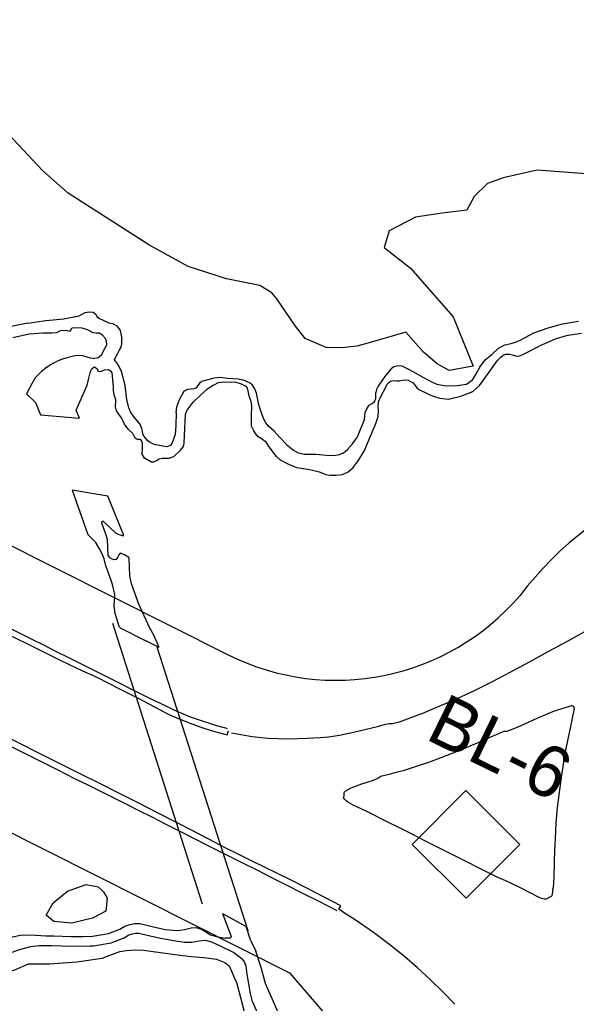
# Model space of a CAD drawing. Extents: x 1517485 to 1521905, y 636528 to 640355.
# Drawn here: x 1519895.6 to 1520112.8, y 638285.4 to 638668.8 of the extents above; entities that cross this region are included whole.
import ezdxf

# ---------------------------------------------------------------- set-up
doc = ezdxf.new("R2010")
doc.units = 0
for name, color, linetype in [('CTL Secondary Horizontal and Vertical CELL', 7, 'Continuous'), ('CTL Secondary Horizontal and Vertical Text', 7, 'Continuous'), ('Exist Hydro Stream or Body of Water', 7, 'Continuous'), ('Exist Right of Way Line', 7, 'Continuous'), ('Exist Roads Curbs', 7, 'Continuous'), ('Exist Roads EOP', 7, 'Continuous'), ('Exist Structure Major Deck Tunnel Box Culvert', 7, 'Continuous'), ('Exist Vegetation Woods Line', 7, 'Continuous')]:
    doc.layers.add(name, color=color, linetype=linetype)

msp = doc.modelspace()

# ---------------------------------------------------------------- linework, layer by layer
at = {"layer": 'CTL Secondary Horizontal and Vertical CELL'}
msp.add_line((1520069.61, 638347.3), (1520069.61, 638347.3), dxfattribs=at)
msp.add_lwpolyline([(1520048.75, 638347.37), (1520069.72, 638368.34), (1520090.72, 638347.34), (1520069.75, 638326.37)], close=True, dxfattribs=at)
at = {"layer": 'Exist Hydro Stream or Body of Water'}
for p, q in [((1519898.81, 638550.48), (1519891.63, 638549.08)), ((1519899.36, 638546.22), (1519893.03, 638544.8)), ((1519959.93, 638506.77), (1519960.29, 638515.04)), ((1520030.18, 638513.06), (1520027.09, 638505.85)), ((1520031.47, 638504.02), (1520034.55, 638511.39)), ((1519934.58, 638431.95), (1519945.16, 638426.56)), ((1519950.02, 638424.07), (1519945.16, 638426.56)), ((1519974.77, 638320.41), (1519983.95, 638315.43)), ((1519985.8, 638309.77), (1519983.95, 638315.43)), ((1519909.03, 638311.73), (1519915.59, 638311.43)), ((1519908.36, 638307.93), (1519915.57, 638307.66)), ((1519915.57, 638307.66), (1519923.09, 638307.77)), ((1519985.8, 638309.77), (1519987.7, 638305.7))]:
    msp.add_line(p, q, dxfattribs=at)
for points in [[(1519898.81, 638550.48), (1519905.84, 638551.5), (1519912.91, 638552.26), (1519918.81, 638553.38), (1519921.21, 638554.69), (1519922.8, 638554.89), (1519924.25, 638554.77), (1519925.4, 638554.06), (1519925.8, 638553.07), (1519926.53, 638552.41), (1519930.37, 638550.68), (1519931.86, 638550.36), (1519933.54, 638549.42), (1519934.83, 638547.6), (1519935.45, 638544.42)], [(1520096.22, 638546.71), (1520101.74, 638548.73), (1520107.41, 638550.25), (1520113.66, 638551.31)], [(1519929.15, 638544.59), (1519927.97, 638545.88), (1519926.6, 638546.64), (1519925.46, 638546.58), (1519924.37, 638546.71), (1519922.14, 638547.95), (1519920.02, 638548.61), (1519916.46, 638548.63), (1519915.84, 638548.39), (1519915.18, 638547.23), (1519914.19, 638547.53), (1519912.39, 638547.69), (1519911.16, 638547.41), (1519909.96, 638546.71), (1519908.14, 638546.66), (1519904.62, 638546.64), (1519899.36, 638546.22)], [(1520079.79, 638538.28), (1520082.42, 638540.8), (1520084.89, 638542.12), (1520087.4, 638542.63), (1520089.44, 638543.27), (1520091.08, 638544.05), (1520096.22, 638546.71)], [(1520114.82, 638546.45), (1520108.84, 638545.59), (1520104.45, 638544.21), (1520098.32, 638541.51)], [(1519924.3, 638536.79), (1519926.21, 638537.07), (1519927.53, 638538.2), (1519928.89, 638540.62), (1519929.58, 638542.12), (1519929.54, 638543.51), (1519929.15, 638544.59)], [(1519933.11, 638535.39), (1519932.67, 638536.2), (1519933.11, 638537.41), (1519933.76, 638538.56), (1519934.5, 638539.88), (1519935.04, 638540.87), (1519935.45, 638542.36), (1519935.45, 638544.42)], [(1520081.93, 638535.82), (1520083.31, 638537.31), (1520084.19, 638538.1), (1520085.31, 638538.49), (1520086.75, 638538.4), (1520088.28, 638538.05), (1520089.48, 638537.6), (1520090.72, 638537.78), (1520092.7, 638538.64), (1520098.32, 638541.51)], [(1519924.3, 638536.79), (1519923.23, 638536.92), (1519920.29, 638537.78), (1519917.68, 638537.89), (1519914.03, 638536.98), (1519911.91, 638536.38), (1519910.23, 638535.73)], [(1520056.02, 638527.78), (1520058.36, 638526.73), (1520062, 638526.06), (1520066.33, 638526.21), (1520069.9, 638526.76), (1520072.24, 638528.41), (1520073.55, 638530.56), (1520075.06, 638533.38), (1520077.2, 638536.17), (1520079.79, 638538.28)], [(1519906.29, 638533.4), (1519907.68, 638534.36), (1519910.23, 638535.73)], [(1519937.48, 638520.77), (1519936.78, 638526.24), (1519935.41, 638531.71), (1519934.62, 638533.42), (1519933.68, 638534.89), (1519933.11, 638535.39)], [(1520056.02, 638527.78), (1520053.03, 638529.39), (1520050.3, 638530.87), (1520047.71, 638532.26), (1520044.78, 638533.71), (1520043.56, 638533.88), (1520042.7, 638533.8), (1520041.62, 638533.49), (1520040.58, 638532.74), (1520038.33, 638530.12), (1520035.43, 638525.95), (1520034.76, 638524.63), (1520034.58, 638523.43)], [(1520054.31, 638523.23), (1520056.86, 638522.08), (1520059.48, 638521.34), (1520062.9, 638520.88), (1520067.67, 638522.12), (1520072.35, 638523.9), (1520074.99, 638526.27), (1520078.8, 638531.36), (1520081.93, 638535.82)], [(1519906.29, 638533.4), (1519903.98, 638531.48), (1519901.71, 638529.2), (1519900.54, 638527.1)], [(1519922.51, 638528.59), (1519923.29, 638531.7), (1519923.8, 638532.7), (1519924.65, 638533.49), (1519925.2, 638533.24), (1519925.83, 638532.74), (1519926.1, 638531.99), (1519926.67, 638531.67), (1519927.55, 638531.84), (1519928.71, 638532.29), (1519930.1, 638532.49), (1519930.94, 638532.09), (1519931.63, 638531.16), (1519931.74, 638529.84), (1519931.84, 638528.23), (1519932.11, 638525.86), (1519932.05, 638524.18), (1519932.34, 638522.7), (1519933.14, 638520.31)], [(1519900.54, 638527.1), (1519899.45, 638525.12), (1519898.26, 638523), (1519901.76, 638519.55), (1519903.72, 638514.8), (1519918.92, 638513.44), (1519917.7, 638516.56), (1519922.02, 638526.34), (1519922.51, 638528.59)], [(1519956.66, 638515.61), (1519956.98, 638517.95), (1519958.16, 638521), (1519959.32, 638523.07), (1519959.94, 638524.11), (1519961.21, 638524.82), (1519962.54, 638524.97), (1519963.78, 638525.08), (1519964.76, 638525.4), (1519965.19, 638526.03), (1519965.59, 638526.74), (1519965.98, 638527.43), (1519966.66, 638527.9), (1519967.76, 638528.13)], [(1519967.76, 638528.13), (1519971.54, 638529.18), (1519973.89, 638529.5), (1519976.88, 638529.11), (1519980.85, 638528.87), (1519982.74, 638528.46)], [(1519982.2, 638526.74), (1519979.68, 638527.48), (1519978.33, 638527.38), (1519975.68, 638527.54), (1519973.04, 638527.24), (1519971.17, 638526.27), (1519968.67, 638524.68)], [(1519993, 638502.33), (1519991.74, 638504.1), (1519989.96, 638505.43), (1519988.67, 638506.18), (1519987.64, 638507.46), (1519986.91, 638508.81), (1519986.12, 638510.37), (1519986.02, 638511.82), (1519986.01, 638513.28), (1519986.09, 638514.79), (1519986.16, 638517.9), (1519986.03, 638519.47), (1519985.62, 638520.72), (1519985.18, 638522.07), (1519984.9, 638523.46), (1519984.64, 638524.6), (1519984.19, 638525.56), (1519983.68, 638525.95), (1519982.2, 638526.74)], [(1519997.13, 638505.93), (1519994.92, 638508.39), (1519992.84, 638510.28), (1519991.62, 638511.69), (1519990.81, 638513.37), (1519989.67, 638516.38), (1519988.91, 638518.73), (1519988.36, 638521.34), (1519987.99, 638523.27), (1519987.33, 638524.91), (1519986.44, 638526.3), (1519985.61, 638527.09), (1519982.74, 638528.46)], [(1520034.55, 638511.39), (1520035.53, 638514.08), (1520035.61, 638516.29), (1520035.44, 638517.95), (1520035.63, 638519.81), (1520036.47, 638521.96), (1520038.41, 638525.57), (1520039.01, 638526.7), (1520039.57, 638527.42), (1520040.33, 638527.9), (1520041.33, 638528.16), (1520042.8, 638528.02), (1520043.81, 638528.03), (1520044.94, 638528.23), (1520046.15, 638528.41), (1520047.11, 638528.25), (1520048.07, 638527.79), (1520049.1, 638527.22), (1520049.83, 638526.38), (1520050.63, 638525.14), (1520051.83, 638524.34), (1520054.31, 638523.23)], [(1519960.29, 638515.04), (1519960.92, 638516.63), (1519963.37, 638519.75), (1519966.26, 638522.64), (1519968.67, 638524.68)], [(1520030.18, 638513.06), (1520030.45, 638515.65), (1520031.08, 638517.15), (1520031.97, 638518.5), (1520033.19, 638519.15), (1520033.98, 638519.99), (1520034.62, 638521.21), (1520034.58, 638523.43)], [(1519939.84, 638507.5), (1519937.93, 638509.23), (1519936.55, 638511.2), (1519935.97, 638512.34), (1519935.41, 638513.63), (1519934.38, 638514.99), (1519933.47, 638516.37), (1519933.07, 638517.93), (1519933.14, 638520.31)], [(1519942.54, 638511.25), (1519940.32, 638513.84), (1519938.93, 638516.01), (1519938.16, 638517.48), (1519937.48, 638520.77)], [(1519956.66, 638515.61), (1519956.6, 638510.59), (1519956.3, 638507.14), (1519955.16, 638503.87), (1519954.45, 638502.8), (1519953.08, 638502.36), (1519951.45, 638502.57), (1519948.06, 638503.21), (1519946.48, 638504.06)], [(1519946.48, 638504.06), (1519945.66, 638504.68), (1519944.14, 638506.31), (1519943.68, 638507.28), (1519943.54, 638508.43), (1519943.32, 638509.52), (1519942.54, 638511.25)], [(1519946.76, 638496.53), (1519944.28, 638497.89), (1519943.48, 638499.46), (1519943.5, 638501.48), (1519943.53, 638503.66), (1519943.17, 638504.77), (1519942.5, 638505.16), (1519941.63, 638505.2), (1519941.08, 638505.47), (1519940.64, 638505.74), (1519939.84, 638507.5)], [(1519946.76, 638496.53), (1519948.02, 638496.46), (1519949.05, 638497.05), (1519950.03, 638497.6), (1519951.26, 638497.89), (1519952.48, 638497.86), (1519953.91, 638497.84), (1519955.81, 638498.59), (1519958.39, 638500.95), (1519959.48, 638502.42), (1519959.81, 638503.7), (1519959.93, 638506.77)], [(1519997.13, 638505.93), (1519999.85, 638503.08), (1520002.47, 638500.99), (1520004.26, 638499.98), (1520006.74, 638499.41), (1520011.1, 638499.48), (1520016.71, 638498.91)], [(1520020.35, 638499.35), (1520021.96, 638499.98), (1520023.55, 638501.3), (1520025.51, 638503.52), (1520027.09, 638505.85)], [(1520021.55, 638491.58), (1520023.79, 638492.6), (1520025.74, 638494.27), (1520027.69, 638496.92), (1520030.03, 638500.66), (1520031.47, 638504.02)], [(1520014.95, 638491.56), (1520012.59, 638492.47), (1520008.73, 638493.31), (1520003.78, 638494.11), (1520000.42, 638495.5), (1519997.43, 638497.18), (1519995.88, 638498.6), (1519993, 638502.33)], [(1520016.71, 638498.91), (1520018.78, 638499.04), (1520020.35, 638499.35)], [(1520014.95, 638491.56), (1520016.69, 638491.26), (1520019.05, 638491.27), (1520021.55, 638491.58)], [(1519929.31, 638468.26), (1519927.66, 638472.51), (1519927.72, 638473.13), (1519927.87, 638473.4), (1519928.15, 638473.29), (1519933, 638468.84), (1519934.1, 638468.26), (1519935.63, 638467.75), (1519936.26, 638467.78), (1519930.01, 638483.14), (1519916.08, 638485.4), (1519922.29, 638468.11)], [(1519932.56, 638440.27), (1519932.72, 638444.75), (1519931.9, 638448.64), (1519930.35, 638453.17), (1519929.31, 638455.96), (1519928.6, 638458.66), (1519927.69, 638460.85), (1519926.8, 638462.57), (1519925.35, 638465.04), (1519922.29, 638468.11)], [(1519942.07, 638440.93), (1519939.23, 638448.92), (1519938.58, 638452.07), (1519938.39, 638458.8), (1519938.25, 638459.23), (1519936.52, 638460.26), (1519934.88, 638460.9), (1519934.32, 638460.18), (1519933.78, 638459.21), (1519933.32, 638458.45), (1519932.53, 638458.28), (1519931.77, 638458.51), (1519930.86, 638459.03), (1519930.19, 638460.05), (1519929.92, 638466.23), (1519929.31, 638468.26)], [(1519934.58, 638431.95), (1519933.5, 638435.32), (1519932.92, 638437.32), (1519932.67, 638439.3), (1519932.56, 638440.27)], [(1519950.02, 638424.07), (1519948.02, 638428.91), (1519946.3, 638431.95), (1519942.07, 638440.93)], [(1519974.77, 638320.41), (1519978.14, 638311.52), (1519977.97, 638311.14), (1519977.78, 638310.88), (1519975.73, 638310.86)], [(1519915.59, 638311.43), (1519920.44, 638311.46), (1519924.08, 638311.54), (1519930.35, 638312.62), (1519934.73, 638314.31), (1519936.66, 638315.48), (1519938.64, 638316.15), (1519940.47, 638316.54), (1519942.51, 638316.55), (1519947.36, 638315.35), (1519952.39, 638314.24), (1519957.23, 638313.79), (1519959.95, 638314.21), (1519962.49, 638314.85), (1519964.42, 638315.04), (1519966.79, 638314.26), (1519970.06, 638312.15), (1519972.47, 638311.42), (1519975.73, 638310.86)], [(1519796.09, 638309.66), (1519798.77, 638310.84), (1519801.33, 638311.41), (1519806.51, 638311.34), (1519817.72, 638310.97), (1519832.93, 638311.87), (1519838.42, 638311.81), (1519845.43, 638310.69), (1519851.87, 638309.3), (1519856, 638307.83), (1519861.3, 638305.25), (1519863.49, 638304.51), (1519865.74, 638304.25), (1519870.23, 638304.61), (1519876.78, 638305.86), (1519885.9, 638308.84), (1519892.83, 638311.35), (1519896.02, 638312.03), (1519899.91, 638312.08), (1519905.8, 638311.77)], [(1519905.8, 638311.77), (1519909.03, 638311.73)], [(1519923.09, 638307.77), (1519924.45, 638307.8), (1519931.35, 638308.99), (1519936.39, 638310.94), (1519938.25, 638312.06), (1519939.64, 638312.53), (1519940.87, 638312.8), (1519942.06, 638312.8), (1519946.51, 638311.7), (1519950.52, 638310.82)], [(1519798.23, 638303.99), (1519800.74, 638304.84), (1519804.16, 638305.48), (1519807.94, 638305.25), (1519818.62, 638305.19), (1519833.1, 638305.99), (1519836.71, 638305.98), (1519841.35, 638305.67), (1519846.28, 638304.78), (1519851.02, 638303.27), (1519855.89, 638301.41), (1519859.61, 638299.48), (1519863.25, 638298.16), (1519865.83, 638297.55), (1519868.76, 638297.61), (1519872.06, 638297.89), (1519877.13, 638298.77), (1519888.78, 638303.91), (1519895.53, 638306.36), (1519899.97, 638307.58), (1519903.23, 638308.02), (1519905.75, 638307.97)], [(1519905.75, 638307.97), (1519908.36, 638307.93)], [(1519950.52, 638310.82), (1519954.96, 638309.98), (1519959.82, 638309.32), (1519962.81, 638309.22), (1519965.61, 638309.78), (1519968.08, 638309.98), (1519970.44, 638309.41), (1519974.12, 638307.67)], [(1519974.12, 638307.67), (1519979.13, 638305.22), (1519981.27, 638303.68), (1519982.43, 638302.82)], [(1520020.42, 638250.22), (1520016.58, 638253.99), (1520011.94, 638259.12), (1520008.2, 638263.41), (1520003.62, 638269.13), (1520000.44, 638274.28), (1519997.33, 638279.82), (1519991.48, 638293.15), (1519989.8, 638299.36), (1519987.7, 638305.7)], [(1519986.49, 638286.15), (1519985.65, 638289.26), (1519984.34, 638296.83), (1519983.93, 638299.91), (1519983.15, 638301.91), (1519982.43, 638302.82)], [(1519992.68, 638273.03), (1519990.72, 638276.52), (1519986.49, 638286.15)]]:
    msp.add_lwpolyline(points, dxfattribs=at)
at = {"layer": 'Exist Right of Way Line'}
for p, q in [((1519196.36, 638813.06), (1519977, 638421.24)), ((1519230.66, 638683.96), (1520000.91, 638297.35)), ((1520000.91, 638297.35), (1520402.4, 637833.27))]:
    msp.add_line(p, q, dxfattribs=at)
for centre, radius, start, end in [((1520201.87, 638359.23), 140, 82.1191, 142.5845), ((1520019.06, 638505.64), 94.3, 243.5116, 319.4177)]:
    msp.add_arc(centre, radius, start, end, dxfattribs=at)
at = {"layer": 'Exist Roads Curbs'}
for points in [[(1519890.97, 638432.06), (1519895.68, 638429.72), (1519900.4, 638427.37), (1519905.16, 638424.99), (1519909.91, 638422.61), (1519914.65, 638420.23), (1519919.36, 638417.87), (1519924.06, 638415.51), (1519932.87, 638411.09), (1519940.58, 638407.23), (1519946.6, 638404.24), (1519950.38, 638402.39), (1519952.85, 638401.22), (1519954.98, 638400.22), (1519956.93, 638399.33), (1519958.86, 638398.48), (1519960.86, 638397.66), (1519962.98, 638396.84), (1519965.23, 638396.03), (1519967.64, 638395.23), (1519970.07, 638394.46), (1519972.41, 638393.77), (1519974.31, 638393.23), (1519975.45, 638392.9), (1519976.25, 638392.65), (1519976.63, 638392.53)], [(1519891.82, 638385.84), (1519897.79, 638382.84), (1519904.26, 638379.57), (1519910.76, 638376.29), (1519916.83, 638373.24), (1519922.48, 638370.42), (1519927.69, 638367.82), (1519932.66, 638365.34), (1519937.56, 638362.89), (1519942.39, 638360.47), (1519947.15, 638358.07), (1519952.12, 638355.56), (1519957.56, 638352.81), (1519963.48, 638349.83), (1519969.87, 638346.6), (1519976.34, 638343.34), (1519982.5, 638340.23), (1519988.36, 638337.28), (1519993.9, 638334.48), (1519999.53, 638331.64), (1520005.66, 638328.55), (1520012.28, 638325.21), (1520019.35, 638321.65)]]:
    msp.add_lwpolyline(points, dxfattribs=at)
at = {"layer": 'Exist Roads EOP'}
for points in [[(1519978.23, 638390.84), (1519986.27, 638389.39), (1519992.5, 638388.81), (1520000.34, 638388.53), (1520007.78, 638388.71), (1520012.98, 638388.99), (1520016.07, 638389.3), (1520020.35, 638389.95), (1520025.87, 638391.13), (1520030.73, 638392.3), (1520035.15, 638393.37), (1520038.37, 638394.18), (1520039.77, 638394.43), (1520040.86, 638394.49), (1520041.07, 638394.5), (1520041.62, 638394.58), (1520043.78, 638395.2), (1520047.92, 638396.63), (1520052.88, 638398.56), (1520059.25, 638401.24), (1520066.05, 638404.15), (1520073.03, 638407.29), (1520079.86, 638410.72), (1520087.18, 638414.59), (1520094.51, 638418.55), (1520101.78, 638422.51), (1520109, 638426.45), (1520116.08, 638430.38)], [(1519890.95, 638429.33), (1519898.43, 638425.64), (1519905.52, 638422.14), (1519911.98, 638418.94), (1519920.09, 638415), (1519924.3, 638413.17), (1519926.72, 638412.04), (1519929.27, 638410.69), (1519935.87, 638407.36), (1519942.42, 638404.11), (1519946.03, 638402.17), (1519950.42, 638399.81), (1519953.61, 638398.15), (1519957.2, 638396.53), (1519962.18, 638394.6), (1519966.34, 638393.09), (1519970.68, 638391.69), (1519976.58, 638390.01), (1519977.03, 638391.68)], [(1520025.76, 638362.72), (1520023.95, 638363.68), (1520022.99, 638364.34), (1520022.01, 638365.42), (1520022.26, 638366.31), (1520022.25, 638366.92), (1520022.21, 638367.1), (1520022.2, 638367.28), (1520022.21, 638367.46), (1520022.25, 638367.62), (1520022.35, 638367.8), (1520022.54, 638368.01), (1520022.84, 638368.23), (1520024.98, 638369.38), (1520029.05, 638370.95), (1520033.61, 638372.42), (1520034.58, 638372.79), (1520035.63, 638373.34), (1520036.08, 638373.63), (1520036.25, 638373.76), (1520036.37, 638373.87), (1520036.44, 638373.98), (1520040.27, 638374.89), (1520043.05, 638375.59), (1520045.74, 638376.34), (1520048.09, 638377.06), (1520050.85, 638377.96), (1520055.18, 638379.44), (1520060.06, 638381.18), (1520064.78, 638383.03), (1520068.7, 638384.65), (1520071.34, 638385.73), (1520074.86, 638387.26), (1520078.46, 638388.86), (1520081.62, 638390.21), (1520084, 638391.23), (1520084.63, 638391.47), (1520084.75, 638391.5), (1520085.74, 638391.47), (1520090.13, 638393.21), (1520094.11, 638394.99), (1520097.72, 638396.63), (1520100.81, 638397.97), (1520103.62, 638399.14), (1520105.56, 638399.87), (1520107.2, 638400.38), (1520109.3, 638401), (1520110.69, 638401.42), (1520110.81, 638401.45), (1520110.93, 638401.46), (1520111.06, 638401.45), (1520111.2, 638401.43), (1520111.32, 638401.4), (1520111.43, 638401.35), (1520111.52, 638401.28), (1520111.59, 638401.2), (1520111.65, 638401.11), (1520111.75, 638400.86), (1520111.8, 638400.71), (1520111.84, 638400.52), (1520111.85, 638400.3), (1520111.8, 638399.7), (1520111.32, 638397.15), (1520110.38, 638392.73), (1520109.3, 638387.84), (1520108.51, 638384.07), (1520107.82, 638380.18), (1520107.06, 638375.21), (1520106.18, 638368.67), (1520105.31, 638361.72), (1520104.79, 638355.6), (1520104.44, 638349.57), (1520104.24, 638344.96), (1520104.17, 638340.74), (1520103.98, 638334.62), (1520103.72, 638330.41), (1520103.52, 638329.48), (1520103.43, 638329.01), (1520103.31, 638327.79), (1520103.26, 638327.57), (1520103.21, 638327.41), (1520103.15, 638327.28), (1520103.05, 638327.16), (1520102.94, 638327.06), (1520102.22, 638326.65), (1520101.25, 638326.17), (1520100.82, 638326.02), (1520100.61, 638325.99), (1520100.42, 638325.98), (1520100.23, 638326.01), (1520099.12, 638326.34), (1520097.79, 638326.91), (1520094.72, 638328.49), (1520090.96, 638330.44), (1520088.04, 638331.87), (1520085.26, 638333.14), (1520083.42, 638333.94), (1520081.63, 638334.75), (1520076.47, 638337.33), (1520068.19, 638341.47), (1520060.96, 638345.07), (1520053.38, 638348.94), (1520048.69, 638351.34), (1520043.77, 638353.82), (1520039, 638356.2), (1520030.54, 638360.4), (1520025.76, 638362.72)], [(1520065.43, 638285.08), (1520060.69, 638289.94), (1520055.77, 638294.66), (1520050.79, 638299.31), (1520045.8, 638303.7), (1520040.08, 638308.28), (1520033.65, 638313.08), (1520026.48, 638317.98), (1520021.94, 638320.87), (1520020.19, 638322.08), (1520020.93, 638323.48), (1520014.72, 638326.71), (1520007.42, 638330.45), (1520001, 638333.7), (1519995.94, 638336.17), (1519986.39, 638340.8), (1519980.9, 638343.54), (1519976.1, 638345.94), (1519971.64, 638348.27), (1519963.46, 638352.57), (1519956.75, 638355.91), (1519949.44, 638359.61), (1519941.8, 638363.52), (1519934.28, 638367.34), (1519926.88, 638371.06), (1519918.97, 638375.01), (1519910.62, 638379.17), (1519902.84, 638383.06), (1519895.73, 638386.63), (1519888.91, 638390.05)]]:
    msp.add_lwpolyline(points, dxfattribs=at)
at = {"layer": 'Exist Structure Major Deck Tunnel Box Culvert'}
for p, q in [((1519967, 638324.09), (1519931.99, 638433.4)), ((1519949.17, 638424.38), (1519984.63, 638313.81))]:
    msp.add_line(p, q, dxfattribs=at)
at = {"layer": 'Exist Vegetation Woods Line'}
for points in [[(1520046.25, 638546.95), (1520031.44, 638542.66), (1520027.2, 638541.53), (1520021.34, 638540.87), (1520015.23, 638541.02), (1520007.02, 638544.49), (1520003.17, 638549.31), (1519995.95, 638559.97), (1519994, 638562.33), (1519989.26, 638565.18), (1519976.34, 638567.78), (1519961.41, 638572.53), (1519946.08, 638581.04), (1519914.53, 638601.22), (1519904.53, 638610.01), (1519889.51, 638626.07), (1519866.87, 638642.9), (1519857.27, 638652), (1519843.15, 638666.76), (1519826.88, 638687.24), (1519808.24, 638716.3), (1519782.74, 638746.26), (1519752.52, 638785.77)], [(1520116.63, 638608.74), (1520097.42, 638610.12), (1520084.26, 638607.15), (1520078.11, 638604.9), (1520072.88, 638599.83), (1520070.02, 638594.51), (1520060.37, 638593.36), (1520049.98, 638591.83), (1520039.79, 638586.49), (1520037.79, 638580.01), (1520048.08, 638571.94), (1520064.7, 638552.95), (1520072.46, 638533.69), (1520063.21, 638532.01), (1520058.43, 638534.6), (1520053.17, 638539.24), (1520046.25, 638546.95)], [(1519929.24, 638321.36), (1519924.08, 638318.58), (1519915.93, 638316.66), (1519908.94, 638317.3), (1519906.04, 638319.76), (1519908.71, 638324.62), (1519914.36, 638329.1), (1519921.64, 638331.8), (1519926.28, 638330.89), (1519928.38, 638328.85), (1519929.77, 638326.47), (1519929.24, 638321.36)], [(1519907.3, 638300.8), (1519917.92, 638301.58), (1519927.79, 638303.02), (1519934.68, 638305.57), (1519937.26, 638306.03), (1519940.7, 638306.33), (1519943.93, 638306.17), (1519957.23, 638304.36), (1519962.47, 638303.68), (1519967.44, 638303.35), (1519972.35, 638302.64), (1519975.6, 638301.28), (1519977.37, 638300.04), (1519980.38, 638293.14), (1519983.54, 638280.72)], [(1519763.51, 638242.75), (1519772.84, 638246.83), (1519781.93, 638254.84), (1519791, 638268.19), (1519796.76, 638278.48), (1519799.99, 638284.12), (1519804.62, 638288.48), (1519811.57, 638291.88), (1519818.91, 638294.02), (1519826.57, 638295.33), (1519834.55, 638296.36), (1519845.34, 638296.91), (1519855.27, 638295.94), (1519863.16, 638294.54), (1519870.98, 638293.49), (1519878.35, 638293.51), (1519893.76, 638298.46), (1519899.03, 638300.76), (1519907.3, 638300.8)]]:
    msp.add_lwpolyline(points, dxfattribs=at)

# ---------------------------------------------------------------- texts
at = {"layer": 'CTL Secondary Horizontal and Vertical Text'}
msp.add_text('BL-6', height=20, rotation=333.9377, dxfattribs=at).set_placement((1520053.36, 638388.64))

doc.saveas('drawing.dxf')
